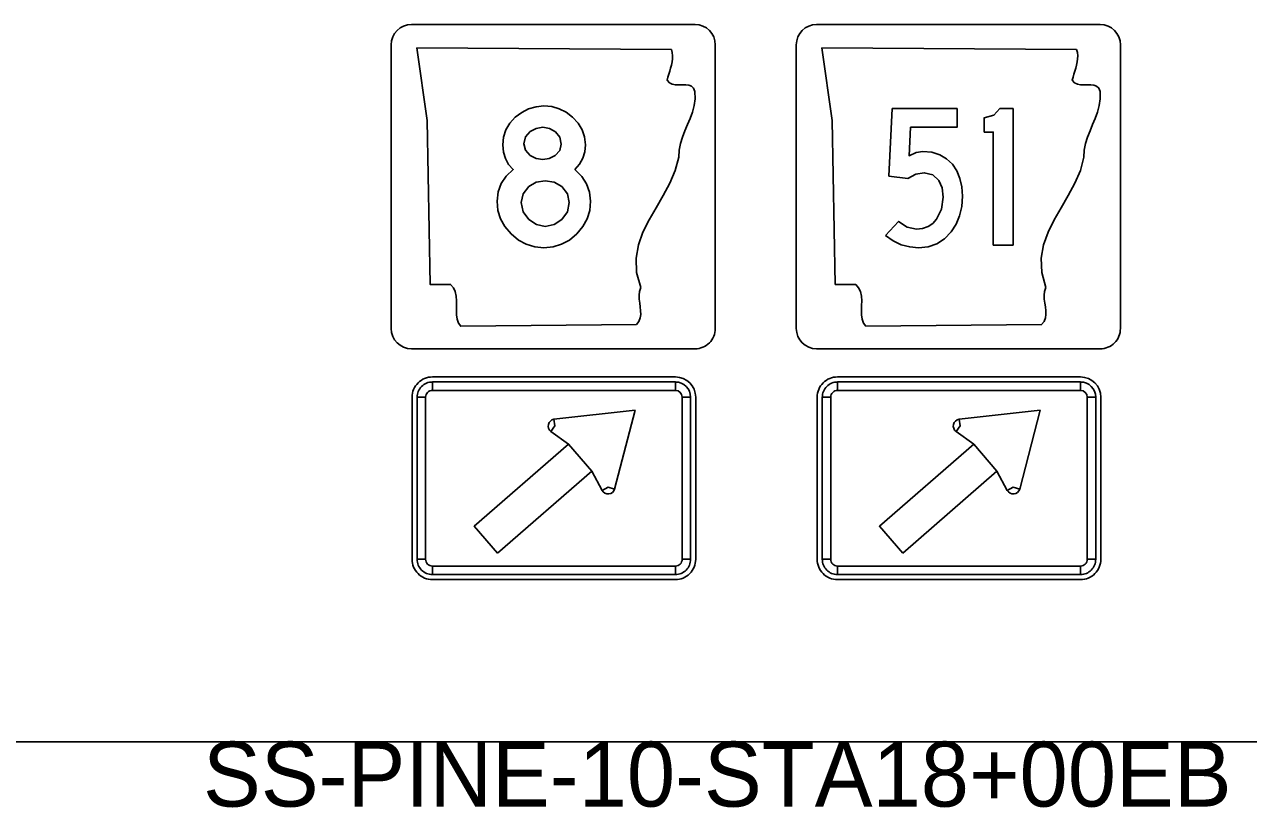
# Model space of a CAD drawing. Extents: x 1001568 to 1002149, y 1840825 to 1841423.
# Drawn here: x 1001937.13 to 1001944.68, y 1841295.06 to 1841299.89 of the extents above; entities that cross this region are included whole.
import ezdxf

# ---------------------------------------------------------------- set-up
doc = ezdxf.new("R2010")
doc.units = 0
for name, color, linetype in [('40', 7, 'Continuous'), ('R_No Plot', 7, 'Continuous'), ('SIGNS', 7, 'Continuous')]:
    doc.layers.add(name, color=color, linetype=linetype)

msp = doc.modelspace()

# ---------------------------------------------------------------- linework, layer by layer
at = {"layer": 'R_No Plot'}
msp.add_line((1001890.6501, 1841295.4691), (1001982.1327, 1841295.4691), dxfattribs=at)
at = {"layer": 'SIGNS'}
for p, q in [((1001941.2658, 1841299.8928), (1001939.5158, 1841299.8928)), ((1001943.7658, 1841299.8928), (1001942.0158, 1841299.8928)), ((1001939.3908, 1841299.7678), (1001939.3908, 1841298.0178)), ((1001941.3908, 1841298.0178), (1001941.3908, 1841299.7678)), ((1001941.8908, 1841299.7678), (1001941.8908, 1841298.0178)), ((1001943.8908, 1841298.0178), (1001943.8908, 1841299.7678)), ((1001939.3908, 1841298.0178), (1001939.3908, 1841298.0178)), ((1001941.8908, 1841298.0178), (1001941.8908, 1841298.0178)), ((1001939.5158, 1841297.8928), (1001941.2658, 1841297.8928)), ((1001942.0158, 1841297.8928), (1001943.7658, 1841297.8928)), ((1001939.6447, 1841297.7191), (1001941.1447, 1841297.7191)), ((1001939.6447, 1841297.6879), (1001939.6447, 1841297.6358)), ((1001941.1447, 1841297.6358), (1001941.1447, 1841297.6879)), ((1001942.1447, 1841297.7191), (1001943.6447, 1841297.7191)), ((1001942.1447, 1841297.6879), (1001942.1447, 1841297.6358)), ((1001943.6447, 1841297.6358), (1001943.6447, 1841297.6879)), ((1001939.5197, 1841296.5941), (1001939.5197, 1841297.5941)), ((1001939.6031, 1841297.5941), (1001939.551, 1841297.5941)), ((1001941.2385, 1841297.5941), (1001941.1864, 1841297.5941)), ((1001941.2697, 1841297.5941), (1001941.2697, 1841296.5941)), ((1001942.0197, 1841296.5941), (1001942.0197, 1841297.5941)), ((1001942.1031, 1841297.5941), (1001942.051, 1841297.5941)), ((1001943.7385, 1841297.5941), (1001943.6864, 1841297.5941)), ((1001943.7697, 1841297.5941), (1001943.7697, 1841296.5941)), ((1001940.4011, 1841297.4165), (1001940.3948, 1841297.4577)), ((1001942.9011, 1841297.4165), (1001942.8948, 1841297.4577)), ((1001940.3766, 1841297.3828), (1001940.4011, 1841297.4165)), ((1001942.8766, 1841297.3828), (1001942.9011, 1841297.4165)), ((1001940.7292, 1841297.0391), (1001940.6924, 1841297.0195)), ((1001940.7691, 1841297.0272), (1001940.7292, 1841297.0391)), ((1001943.2292, 1841297.0391), (1001943.1924, 1841297.0195)), ((1001943.2691, 1841297.0272), (1001943.2292, 1841297.0391)), ((1001939.551, 1841296.5941), (1001939.6031, 1841296.5941)), ((1001939.6447, 1841296.5524), (1001939.6447, 1841296.5004)), ((1001941.1447, 1841296.5004), (1001941.1447, 1841296.5524)), ((1001941.1864, 1841296.5941), (1001941.2385, 1841296.5941)), ((1001942.051, 1841296.5941), (1001942.1031, 1841296.5941)), ((1001942.1447, 1841296.5524), (1001942.1447, 1841296.5004)), ((1001943.6447, 1841296.5004), (1001943.6447, 1841296.5524)), ((1001943.6864, 1841296.5941), (1001943.7385, 1841296.5941)), ((1001941.1447, 1841296.4691), (1001939.6447, 1841296.4691)), ((1001943.6447, 1841296.4691), (1001942.1447, 1841296.4691))]:
    msp.add_line(p, q, dxfattribs=at)
for points in [[(1001939.5158, 1841299.8928), (1001939.5158, 1841299.8928)], [(1001941.2658, 1841299.8928), (1001941.2658, 1841299.8928)], [(1001942.0158, 1841299.8928), (1001942.0158, 1841299.8928)], [(1001943.7658, 1841299.8928), (1001943.7658, 1841299.8928)], [(1001939.3908, 1841299.7678), (1001939.3908, 1841299.7678)], [(1001941.8908, 1841299.7678), (1001941.8908, 1841299.7678)], [(1001940.5237, 1841298.9981), (1001940.5521, 1841299.0314), (1001940.5724, 1841299.068), (1001940.5848, 1841299.108), (1001940.589, 1841299.1513), (1001940.5839, 1841299.1991), (1001940.5691, 1841299.2436), (1001940.5444, 1841299.2847), (1001940.5101, 1841299.3221), (1001940.4703, 1841299.352), (1001940.4281, 1841299.3734), (1001940.3822, 1841299.3863), (1001940.3333, 1841299.3907), (1001940.2846, 1841299.386), (1001940.2389, 1841299.3729), (1001940.1962, 1841299.3509), (1001940.1565, 1841299.3203), (1001940.1226, 1841299.2834), (1001940.0987, 1841299.2429), (1001940.0843, 1841299.1988), (1001940.0796, 1841299.1513), (1001940.0835, 1841299.1059), (1001940.0956, 1841299.0655), (1001940.1157, 1841299.0294), (1001940.1441, 1841298.9981), (1001940.1002, 1841298.9582), (1001940.069, 1841298.9122), (1001940.0502, 1841298.8605), (1001940.0441, 1841298.8026), (1001940.0492, 1841298.7465), (1001940.0654, 1841298.6943), (1001940.0925, 1841298.6459), (1001940.1304, 1841298.6012), (1001940.1756, 1841298.5635), (1001940.2243, 1841298.537), (1001940.2769, 1841298.5211), (1001940.3333, 1841298.516), (1001940.3894, 1841298.5211), (1001940.442, 1841298.537), (1001940.4904, 1841298.5635), (1001940.5354, 1841298.6012), (1001940.5728, 1841298.6459), (1001940.5996, 1841298.6943), (1001940.6158, 1841298.7465), (1001940.6212, 1841298.8026), (1001940.615, 1841298.858), (1001940.5968, 1841298.9094), (1001940.5663, 1841298.9561), (1001940.5237, 1841298.9981)], [(1001940.4401, 1841299.1552), (1001940.4306, 1841299.1155), (1001940.402, 1841299.0843), (1001940.3661, 1841299.0664), (1001940.3261, 1841299.0606), (1001940.2846, 1841299.0664), (1001940.2481, 1841299.0851), (1001940.2186, 1841299.117), (1001940.2091, 1841299.1578), (1001940.2186, 1841299.1991), (1001940.2481, 1841299.2323), (1001940.2846, 1841299.2519), (1001940.3261, 1841299.2586), (1001940.3679, 1841299.2517), (1001940.4043, 1841299.2316), (1001940.4311, 1841299.1975), (1001940.4401, 1841299.1552)], [(1001940.4897, 1841298.7943), (1001940.4784, 1841298.7373), (1001940.4445, 1841298.6902), (1001940.3961, 1841298.6584), (1001940.3416, 1841298.6479), (1001940.2875, 1841298.6584), (1001940.2398, 1841298.6904), (1001940.2042, 1841298.7379), (1001940.1925, 1841298.7943), (1001940.2042, 1841298.849), (1001940.2398, 1841298.8929), (1001940.2862, 1841298.9194), (1001940.3416, 1841298.9285), (1001940.3965, 1841298.9194), (1001940.4433, 1841298.8929), (1001940.478, 1841298.849), (1001940.4897, 1841298.7943)], [(1001939.5158, 1841297.8928), (1001939.5158, 1841297.8928)], [(1001941.2658, 1841297.8928), (1001941.2658, 1841297.8928)], [(1001942.0158, 1841297.8928), (1001942.0158, 1841297.8928)], [(1001943.7658, 1841297.8928), (1001943.7658, 1841297.8928)]]:
    msp.add_lwpolyline(points, dxfattribs=at)
for points in [[(1001941.1207, 1841299.7384), (1001941.1254, 1841299.7194), (1001941.1271, 1841299.6999), (1001941.1264, 1841299.6808), (1001941.1241, 1841299.6617), (1001941.1201, 1841299.6426), (1001941.1153, 1841299.6239), (1001941.1097, 1841299.6048), (1001941.104, 1841299.5865), (1001941.0986, 1841299.5681), (1001941.0936, 1841299.5497), (1001941.1077, 1841299.5336), (1001941.1251, 1841299.5244), (1001941.1448, 1841299.5204), (1001941.1662, 1841299.52), (1001941.1875, 1841299.5207), (1001941.2083, 1841299.5211), (1001941.2273, 1841299.5189), (1001941.244, 1841299.5127), (1001941.2571, 1841299.5006), (1001941.2651, 1841299.4804), (1001941.2657, 1841299.4348), (1001941.2601, 1841299.3923), (1001941.2494, 1841299.3519), (1001941.235, 1841299.3133), (1001941.2193, 1841299.2751), (1001941.2032, 1841299.2373), (1001941.1882, 1841299.1988), (1001941.1762, 1841299.1591), (1001941.1678, 1841299.1176), (1001941.1658, 1841299.0736), (1001941.1438, 1841298.9914), (1001941.11, 1841298.9132), (1001941.0692, 1841298.8375), (1001941.0251, 1841298.7626), (1001940.982, 1841298.6881), (1001940.9442, 1841298.6121), (1001940.9162, 1841298.5336), (1001940.9018, 1841298.451), (1001940.9051, 1841298.3636), (1001940.9309, 1841298.27), (1001940.9232, 1841298.2468), (1001940.9205, 1841298.223), (1001940.9212, 1841298.1991), (1001940.9242, 1841298.1749), (1001940.9276, 1841298.151), (1001940.9302, 1841298.1275), (1001940.9309, 1841298.1044), (1001940.9276, 1841298.0827), (1001940.9192, 1841298.0615), (1001940.9038, 1841298.0416), (1001939.8201, 1841298.0317), (1001939.8054, 1841298.0515), (1001939.7971, 1841298.0754), (1001939.7934, 1841298.1018), (1001939.793, 1841298.1301), (1001939.7937, 1841298.1598), (1001939.794, 1841298.1892), (1001939.792, 1841298.2182), (1001939.7864, 1841298.245), (1001939.7753, 1841298.2692), (1001939.757, 1841298.2898), (1001939.6306, 1841298.2898), (1001939.6126, 1841299.3016), (1001939.5491, 1841299.7484), (1001941.1207, 1841299.7384), (1001941.1207, 1841299.7384)], [(1001943.6207, 1841299.7384), (1001943.6254, 1841299.7194), (1001943.6271, 1841299.6999), (1001943.6264, 1841299.6808), (1001943.6241, 1841299.6617), (1001943.6201, 1841299.6426), (1001943.6153, 1841299.6239), (1001943.6097, 1841299.6048), (1001943.604, 1841299.5865), (1001943.5986, 1841299.5681), (1001943.5936, 1841299.5497), (1001943.6077, 1841299.5336), (1001943.6251, 1841299.5244), (1001943.6448, 1841299.5204), (1001943.6662, 1841299.52), (1001943.6875, 1841299.5207), (1001943.7083, 1841299.5211), (1001943.7273, 1841299.5189), (1001943.744, 1841299.5127), (1001943.7571, 1841299.5006), (1001943.7651, 1841299.4804), (1001943.7657, 1841299.4348), (1001943.7601, 1841299.3923), (1001943.7494, 1841299.3519), (1001943.735, 1841299.3133), (1001943.7193, 1841299.2751), (1001943.7032, 1841299.2373), (1001943.6882, 1841299.1988), (1001943.6762, 1841299.1591), (1001943.6678, 1841299.1176), (1001943.6658, 1841299.0736), (1001943.6438, 1841298.9914), (1001943.61, 1841298.9132), (1001943.5692, 1841298.8375), (1001943.5251, 1841298.7626), (1001943.482, 1841298.6881), (1001943.4442, 1841298.6121), (1001943.4162, 1841298.5336), (1001943.4018, 1841298.451), (1001943.4051, 1841298.3636), (1001943.4309, 1841298.27), (1001943.4232, 1841298.2468), (1001943.4205, 1841298.223), (1001943.4212, 1841298.1991), (1001943.4242, 1841298.1749), (1001943.4276, 1841298.151), (1001943.4302, 1841298.1275), (1001943.4309, 1841298.1044), (1001943.4276, 1841298.0827), (1001943.4192, 1841298.0615), (1001943.4038, 1841298.0416), (1001942.3201, 1841298.0317), (1001942.3054, 1841298.0515), (1001942.2971, 1841298.0754), (1001942.2934, 1841298.1018), (1001942.293, 1841298.1301), (1001942.2937, 1841298.1598), (1001942.2941, 1841298.1892), (1001942.292, 1841298.2182), (1001942.2864, 1841298.245), (1001942.2753, 1841298.2692), (1001942.257, 1841298.2898), (1001942.1306, 1841298.2898), (1001942.1126, 1841299.3016), (1001942.0491, 1841299.7484), (1001943.6207, 1841299.7384), (1001943.6207, 1841299.7384)], [(1001942.4411, 1841298.5906), (1001942.4888, 1841298.5576), (1001942.5387, 1841298.5344), (1001942.5909, 1841298.5205), (1001942.6456, 1841298.5159), (1001942.7049, 1841298.5219), (1001942.758, 1841298.54), (1001942.805, 1841298.5705), (1001942.8459, 1841298.6136), (1001942.8766, 1841298.661), (1001942.8985, 1841298.7136), (1001942.9117, 1841298.7712), (1001942.9164, 1841298.8341), (1001942.9125, 1841298.8915), (1001942.9008, 1841298.9437), (1001942.8816, 1841298.9898), (1001942.8544, 1841299.0304), (1001942.8179, 1841299.065), (1001942.7755, 1841299.0899), (1001942.7265, 1841299.1049), (1001942.6719, 1841299.11), (1001942.6306, 1841299.1033), (1001942.587, 1841299.0832), (1001942.5963, 1841299.2586), (1001942.8833, 1841299.2586), (1001942.8833, 1841299.3742), (1001942.4826, 1841299.3742), (1001942.4621, 1841298.9582), (1001942.5785, 1841298.9432), (1001942.6275, 1841298.9692), (1001942.6804, 1841298.978), (1001942.7325, 1841298.9662), (1001942.7704, 1841298.9314), (1001942.79, 1841298.8854), (1001942.7967, 1841298.8284), (1001942.7866, 1841298.7537), (1001942.7567, 1841298.6925), (1001942.7323, 1841298.6654), (1001942.7035, 1841298.6466), (1001942.6703, 1841298.6349), (1001942.6329, 1841298.6314), (1001942.5756, 1841298.643), (1001942.5218, 1841298.6783)], [(1001943.1056, 1841298.5324), (1001943.2286, 1841298.5324), (1001943.2286, 1841299.3742), (1001943.1472, 1841299.3742), (1001943.109, 1841299.3329), (1001943.0505, 1841299.3174), (1001943.0505, 1841299.2292), (1001943.1056, 1841299.2292)], [(1001939.6447, 1841297.6879), (1001941.1447, 1841297.6879), (1001941.1447, 1841297.6358), (1001939.6447, 1841297.6358), (1001939.6447, 1841297.6879), (1001939.6447, 1841297.6879)], [(1001942.1447, 1841297.6879), (1001943.6447, 1841297.6879), (1001943.6447, 1841297.6358), (1001942.1447, 1841297.6358), (1001942.1447, 1841297.6879), (1001942.1447, 1841297.6879)], [(1001939.551, 1841296.5941), (1001939.551, 1841297.5941), (1001939.6031, 1841297.5941), (1001939.6031, 1841296.5941), (1001939.551, 1841296.5941), (1001939.551, 1841296.5941)], [(1001941.2385, 1841297.5941), (1001941.2385, 1841296.5941), (1001941.1864, 1841296.5941), (1001941.1864, 1841297.5941), (1001941.2385, 1841297.5941), (1001941.2385, 1841297.5941)], [(1001942.051, 1841296.5941), (1001942.051, 1841297.5941), (1001942.1031, 1841297.5941), (1001942.1031, 1841296.5941), (1001942.051, 1841296.5941), (1001942.051, 1841296.5941)], [(1001943.7385, 1841297.5941), (1001943.7385, 1841296.5941), (1001943.6864, 1841296.5941), (1001943.6864, 1841297.5941), (1001943.7385, 1841297.5941), (1001943.7385, 1841297.5941)], [(1001940.8953, 1841297.5148), (1001940.3948, 1841297.4577), (1001940.4011, 1841297.4165), (1001940.3766, 1841297.3828), (1001940.4855, 1841297.3035), (1001940.6291, 1841297.1384), (1001940.6924, 1841297.0195), (1001940.7292, 1841297.0391), (1001940.7691, 1841297.0272), (1001940.8953, 1841297.5148)], [(1001943.3953, 1841297.5148), (1001942.8948, 1841297.4577), (1001942.9011, 1841297.4165), (1001942.8766, 1841297.3828), (1001942.9855, 1841297.3035), (1001943.1291, 1841297.1384), (1001943.1924, 1841297.0195), (1001943.2292, 1841297.0391), (1001943.2691, 1841297.0272), (1001943.3953, 1841297.5148)], [(1001940.0473, 1841296.6327), (1001939.9038, 1841296.7978), (1001940.4855, 1841297.3035), (1001940.6291, 1841297.1384), (1001940.0473, 1841296.6327)], [(1001942.5473, 1841296.6327), (1001942.4038, 1841296.7978), (1001942.9855, 1841297.3035), (1001943.1291, 1841297.1384), (1001942.5473, 1841296.6327)], [(1001941.1447, 1841296.5004), (1001939.6447, 1841296.5004), (1001939.6447, 1841296.5524), (1001941.1447, 1841296.5524), (1001941.1447, 1841296.5004), (1001941.1447, 1841296.5004)], [(1001943.6447, 1841296.5004), (1001942.1447, 1841296.5004), (1001942.1447, 1841296.5524), (1001943.6447, 1841296.5524), (1001943.6447, 1841296.5004), (1001943.6447, 1841296.5004)]]:
    msp.add_lwpolyline(points, close=True, dxfattribs=at)
for centre, radius, start, end in [((1001939.5158, 1841299.7678), 0.125, 90.00021, 179.99985), ((1001941.2658, 1841299.7678), 0.125, 0, 90), ((1001942.0158, 1841299.7678), 0.125, 90.00021, 179.99985), ((1001943.7658, 1841299.7678), 0.125, 0, 90), ((1001939.5158, 1841298.0178), 0.125, 180, 270), ((1001941.2658, 1841298.0178), 0.125, 270.00006, 0.00027), ((1001942.0158, 1841298.0178), 0.125, 180, 270), ((1001943.7658, 1841298.0178), 0.125, 270.00006, 0.00027), ((1001939.6447, 1841297.5941), 0.125, 89.99979, 180), ((1001939.6447, 1841297.5941), 0.0937, 89.99979, 180), ((1001941.1447, 1841297.5941), 0.125, 0.00015, 89.99979), ((1001941.1447, 1841297.5941), 0.0937, 0.00015, 89.99979), ((1001942.1447, 1841297.5941), 0.125, 89.99979, 180), ((1001942.1447, 1841297.5941), 0.0937, 89.99979, 180), ((1001943.6447, 1841297.5941), 0.125, 0.00015, 89.99979), ((1001943.6447, 1841297.5941), 0.0937, 0.00015, 89.99979), ((1001939.6447, 1841297.5941), 0.0417, 89.99979, 180), ((1001941.1447, 1841297.5941), 0.0417, 0.00015, 89.99979), ((1001942.1447, 1841297.5941), 0.0417, 89.99979, 180), ((1001943.6447, 1841297.5941), 0.0417, 0.00015, 89.99979), ((1001940.4011, 1841297.4165), 0.0417, 98.72435, 233.95041), ((1001942.9011, 1841297.4165), 0.0417, 98.72435, 233.95041), ((1001940.7292, 1841297.0391), 0.0417, 208.04986, 343.27592), ((1001943.2292, 1841297.0391), 0.0417, 208.04986, 343.27592), ((1001939.6447, 1841296.5941), 0.125, 179.99973, 269.99994), ((1001939.6447, 1841296.5941), 0.0937, 179.99973, 269.99994), ((1001939.6447, 1841296.5941), 0.0417, 179.99973, 269.99994), ((1001941.1447, 1841296.5941), 0.0937, 269.99994, 0.00015), ((1001941.1447, 1841296.5941), 0.0417, 269.99994, 0.00015), ((1001941.1447, 1841296.5941), 0.125, 269.99994, 0.00015), ((1001942.1447, 1841296.5941), 0.125, 179.99973, 269.99994), ((1001942.1447, 1841296.5941), 0.0937, 179.99973, 269.99994), ((1001942.1447, 1841296.5941), 0.0417, 179.99973, 269.99994), ((1001943.6447, 1841296.5941), 0.0937, 269.99994, 0.00015), ((1001943.6447, 1841296.5941), 0.0417, 269.99994, 0.00015), ((1001943.6447, 1841296.5941), 0.125, 269.99994, 0.00015)]:
    msp.add_arc(centre, radius, start, end, dxfattribs=at)

# ---------------------------------------------------------------- texts
at = {"layer": '40'}
msp.add_text('SS-PINE-10-STA18+00EB', height=0.4, rotation=0, dxfattribs=at).set_placement((1001938.2295, 1841295.0691))

doc.saveas('drawing.dxf')
